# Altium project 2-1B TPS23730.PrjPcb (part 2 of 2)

## Sheet TPS23730 Page 1 Input Power.SchDoc
size A2; Date: Not shown in title block; ApprovedBy: Not shown in title block; CheckedBy: Not shown in title block; Author: Not shown in title block; CompanyName: Not shown in title block; Engineer: Not shown in title block; Organization: Not shown in title block; Address1: Not shown in title block; Address2: Not shown in title block; Address3: Not shown in title block; Address4: Not shown in title block; DocumentNumber: 2; Revision: Use project parameter SCH_Rev; SheetNumber: 2; SheetTotal: 3; PageSetup: Record=PageOptions¦CenterHorizontal=True¦CenterVertical=True¦PrintScale=1.00¦XCorrection=1.00¦YCorrection=1.00¦PrintKind=0¦BorderSize=5000000¦LeftOffset=0¦BottomOffset=0¦Orientation=2¦PaperLength=1000¦PaperWidth=1000¦Scale=100¦PaperSource=15¦PrintQuality=600¦MediaType=1¦DitherType=10¦PaperKind=Letter¦PrintScaleMode=1
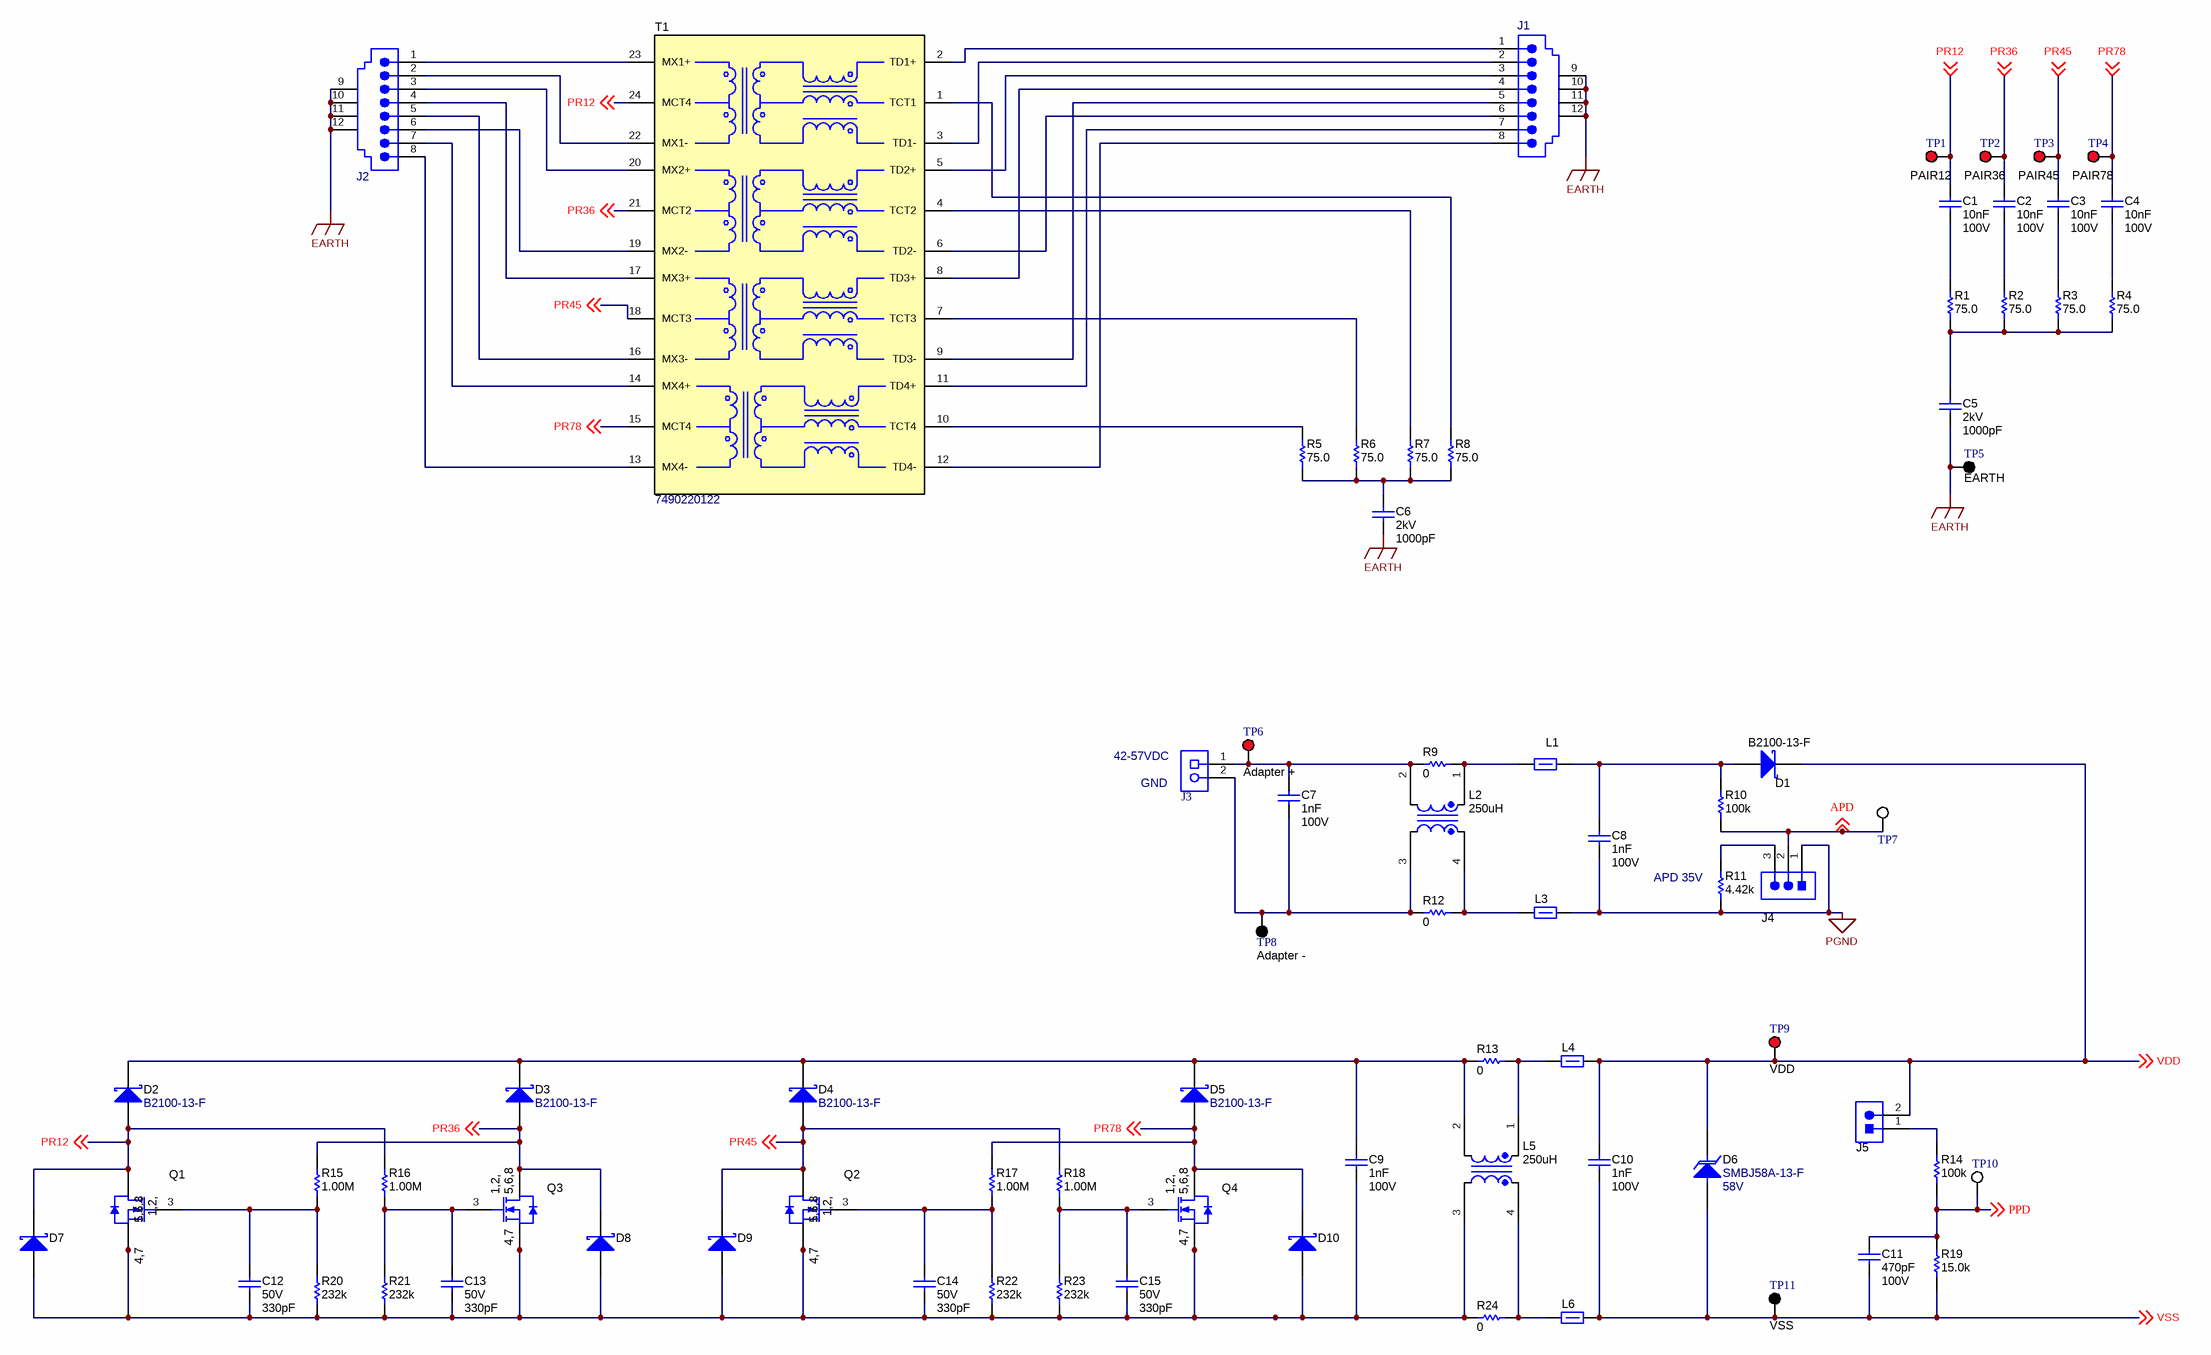
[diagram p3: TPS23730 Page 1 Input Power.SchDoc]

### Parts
C1  Cap_F: 10nF  VDC_V: 100V  [0603]  (hidden comment: CGA3E2X7R2A103K080AA)
C2  Cap_F: 10nF  VDC_V: 100V  [0603]  (hidden comment: CGA3E2X7R2A103K080AA)
C3  Cap_F: 10nF  VDC_V: 100V  [0603]  (hidden comment: CGA3E2X7R2A103K080AA)
C4  Cap_F: 10nF  VDC_V: 100V  [0603]  (hidden comment: CGA3E2X7R2A103K080AA)
C5  VDC_V: 2kV  ValueDisplayed: 1000pF  [1808]  (hidden comment: GR442QR73D102KW01L)
C6  VDC_V: 2kV  ValueDisplayed: 1000pF  [1808]  (hidden comment: GR442QR73D102KW01L)
C7  Cap_F: 1nF  VDC_V: 100V  [0603]  (hidden comment: C1608X7R2A102K080AA)
C8  Cap_F: 1nF  VDC_V: 100V  [0603]  (hidden comment: C1608X7R2A102K080AA)
C9  Cap_F: 1nF  VDC_V: 100V  [0603]  (hidden comment: C1608X7R2A102K080AA)
C10  Cap_F: 1nF  VDC_V: 100V  [0603]  (hidden comment: C1608X7R2A102K080AA)
C11  Cap_F: 470pF  VDC_V: 100V  [0805_HV]  (hidden comment: 08051C471KAT2A)
C12  VDC_V: 50V  ValueDisplayed: 330pF  [0603]  (hidden comment: 885012006060)
C13  VDC_V: 50V  ValueDisplayed: 330pF  [0603]  (hidden comment: 885012006060)
C14  VDC_V: 50V  ValueDisplayed: 330pF  [0603]  (hidden comment: 885012006060)
C15  VDC_V: 50V  ValueDisplayed: 330pF  [0603]  (hidden comment: 885012006060)
D1  PartNumber: B2100-13-F  [SMB]  (hidden comment: CMP-0028397-2)
D2  B2100-13-F  [SMB]
D3  B2100-13-F  [SMB]
D4  B2100-13-F  [SMB]
D5  B2100-13-F  [SMB]
D6  SMBJ58A-13-F  value 58V  [SMB]
D7  CMP-0028397-2  [SMB]  (value not drawn)
D8  CMP-0028397-2  [SMB]  (value not drawn)
D9  CMP-0028397-2  [SMB]  (value not drawn)
D10  CMP-0028397-2  [SMB]  (value not drawn)
J1  1-406541-1  [TEC_1-406541-1]  (value not drawn)
J2  1-406541-1  [TEC_1-406541-1]  (value not drawn)
J3  39357-0002  [MOLEX_39357-0002]  (value not drawn)
J4  5-146278-3  [TE_5-146278-3]  (value not drawn)
J5  PEC02SAAN  [CONN_PEC02SAAN]  (value not drawn)
L1  742792641  [0603]  (value not drawn)
L2  value 250uH  [WE-SL5]  (hidden comment: 744272251)
L3  742792641  [0603]  (value not drawn)
L4  742792641  [0603]  (value not drawn)
L5  value 250uH  [WE-SL5]  (hidden comment: 744272251)
L6  742792641  [0603]  (value not drawn)
Q1  CSD19538Q2  [DQK0006C]  (value not drawn)
Q2  CSD19538Q2  [DQK0006C]  (value not drawn)
Q3  CSD19538Q2  [DQK0006C]  (value not drawn)
Q4  CSD19538Q2  [DQK0006C]  (value not drawn)
R1  ValueDisplayed: 75.0  [0603]  (hidden comment: CRCW060375R0FKEA)
R2  ValueDisplayed: 75.0  [0603]  (hidden comment: CRCW060375R0FKEA)
R3  ValueDisplayed: 75.0  [0603]  (hidden comment: CRCW060375R0FKEA)
R4  ValueDisplayed: 75.0  [0603]  (hidden comment: CRCW060375R0FKEA)
R5  ValueDisplayed: 75.0  [0603]  (hidden comment: CRCW060375R0FKEA)
R6  ValueDisplayed: 75.0  [0603]  (hidden comment: CRCW060375R0FKEA)
R7  ValueDisplayed: 75.0  [0603]  (hidden comment: CRCW060375R0FKEA)
R8  ValueDisplayed: 75.0  [0603]  (hidden comment: CRCW060375R0FKEA)
R9  ValueDisplayed: 0  [0805_HV]  (hidden comment: PMR10EZPJ000)
R10  ValueDisplayed: 100k  [0603]  (hidden comment: CRCW0603100KFKEA)
R11  ValueDisplayed: 4.42k  [0603]  (hidden comment: CRCW06034K42FKEA)
R12  ValueDisplayed: 0  [0805_HV]  (hidden comment: PMR10EZPJ000)
R13  ValueDisplayed: 0  [0805_HV]  (hidden comment: PMR10EZPJ000)
R14  ValueDisplayed: 100k  [0603]  (hidden comment: CRCW0603100KFKEA)
R15  ValueDisplayed: 1.00M  [0603]  (hidden comment: CRCW06031M00FKEA)
R16  ValueDisplayed: 1.00M  [0603]  (hidden comment: CRCW06031M00FKEA)
R17  ValueDisplayed: 1.00M  [0603]  (hidden comment: CRCW06031M00FKEA)
R18  ValueDisplayed: 1.00M  [0603]  (hidden comment: CRCW06031M00FKEA)
R19  ValueDisplayed: 15.0k  [0603]  (hidden comment: CRCW060315K0FKEA)
R20  ValueDisplayed: 232k  [0603]  (hidden comment: CRCW0603232KFKEA)
R21  ValueDisplayed: 232k  [0603]  (hidden comment: CRCW0603232KFKEA)
R22  ValueDisplayed: 232k  [0603]  (hidden comment: CRCW0603232KFKEA)
R23  ValueDisplayed: 232k  [0603]  (hidden comment: CRCW0603232KFKEA)
R24  ValueDisplayed: 0  [0805_HV]  (hidden comment: PMR10EZPJ000)
T1  7490220122  [Wurth_7490220122]
TP1  PAIR12  [Keystone5010]
TP2  PAIR36  [Keystone5010]
TP3  PAIR45  [Keystone5010]
TP4  PAIR78  [Keystone5010]
TP5  EARTH  [Keystone5011]
TP6  Adapter +  [Keystone5000]
TP7  5002  [Keystone5002]  (value not drawn)
TP8  Adapter -  [Keystone5001]
TP9  VDD  [Keystone5000]
TP10  5002  [Keystone5002]  (value not drawn)
TP11  VSS  [Keystone5001]

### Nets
EARTH: C5.1 C6.1 J1.9 J1.10 J1.11 J1.12 J2.9 J2.10 J2.11 J2.12 TP5.1
PGND: C8.2 J4.1 L3.2 R11.1
APD: J4.2 R10.1 TP7.1 ; off-sheet APD
PPD: C11.1 R14.2 R19.2 TP10.1 ; off-sheet PPD
PR12: C1.2 D2.2(A) D7.1(K) Q1.1(D) Q1.2(D) Q1.5(D) Q1.6(D) Q1.8(D) R16.2 T1.24(MCT4) TP1.1 ; off-sheet PR12
PR36: C2.2 D3.2(A) D8.1(K) Q3.1(D) Q3.2(D) Q3.5(D) Q3.6(D) Q3.8(D) R15.2 T1.21(MCT2) TP2.1 ; off-sheet PR36
PR45: C3.2 D4.2(A) D9.1(K) Q2.1(D) Q2.2(D) Q2.5(D) Q2.6(D) Q2.8(D) R18.2 T1.18(MCT3) TP3.1 ; off-sheet PR45
PR78: C4.2 D5.2(A) D10.1(K) Q4.1(D) Q4.2(D) Q4.5(D) Q4.6(D) Q4.8(D) R17.2 T1.15(MCT4) TP4.1 ; off-sheet PR78
VDD: C10.1 D1.1(K) D6.1(K) J5.2 L4.2 TP9.1 ; off-sheet VDD
VSS: C10.2 C11.2 D6.2(A) L6.2 R19.1 TP11.1 ; off-sheet VSS
NetC1_1: C1.1 R1.1
NetC2_1: C2.1 R2.1
NetC3_1: C3.1 R3.1
NetC4_1: C4.1 R4.1
NetC5_2: C5.2 R1.2 R2.2 R3.2 R4.2
NetC6_2: C6.2 R5.2 R6.2 R7.2 R8.2
NetC7_1: C7.1 J3.1 L2.2 R9.1 TP6.1
NetC7_2: C7.2 J3.2 L2.3 R12.1 TP8.1
NetC8_1: C8.1 D1.2(A) L1.2 R10.2
NetC9_1: C9.1 D2.1(K) D3.1(K) D4.1(K) D5.1(K) L5.2 R13.1
NetC9_2: C9.2 C12.2 C13.2 C14.2 C15.2 D7.2(A) D8.2(A) D9.2(A) D10.2(A) L5.3 Q1.4(S) Q1.7(S) Q2.4(S) Q2.7(S) Q3.4(S) Q3.7(S) Q4.4(S) Q4.7(S) R20.1 R21.1 R22.1 R23.1 R24.1
NetC12_1: C12.1 Q1.3(G) R15.1 R20.2
NetC13_1: C13.1 Q3.3(G) R16.1 R21.2
NetC14_1: C14.1 Q2.3(G) R17.1 R22.2
NetC15_1: C15.1 Q4.3(G) R18.1 R23.2
NetJ1_1: J1.1 T1.2(TD1+)
NetJ1_2: J1.2 T1.3(TD1-)
NetJ1_3: J1.3 T1.5(TD2+)
NetJ1_4: J1.4 T1.8(TD3+)
NetJ1_5: J1.5 T1.9(TD3-)
NetJ1_6: J1.6 T1.6(TD2-)
NetJ1_7: J1.7 T1.11(TD4+)
NetJ1_8: J1.8 T1.12(TD4-)
NetJ2_1: J2.1 T1.23(MX1+)
NetJ2_2: J2.2 T1.22(MX1-)
NetJ2_3: J2.3 T1.20(MX2+)
NetJ2_4: J2.4 T1.17(MX3+)
NetJ2_5: J2.5 T1.16(MX3-)
NetJ2_6: J2.6 T1.19(MX2-)
NetJ2_7: J2.7 T1.14(MX4+)
NetJ2_8: J2.8 T1.13(MX4-)
NetJ4_3: J4.3 R11.2
NetJ5_1: J5.1 R14.1
NetL1_1: L1.1 L2.1 R9.2
NetL2_4: L2.4 L3.1 R12.2
NetL4_1: L4.1 L5.1 R13.2
NetL5_4: L5.4 L6.1 R24.2
NetR5_1: R5.1 T1.10(TCT4)
NetR6_1: R6.1 T1.7(TCT3)
NetR7_1: R7.1 T1.4(TCT2)
NetR8_1: R8.1 T1.1(TCT1)

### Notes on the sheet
- (near J3) 42-57VDC
- (near J3) GND
- (near R11) APD 35V

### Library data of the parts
C1-C4 = CMP-0007082-4: CAP, CERM, 0.01 uF, 100 V, +/- 10%, X7R, AEC-Q200 Grade 1, 0603; Manufacturer: TDK; TaMin_C: -55°C; ESR_ohm: 0.235428; Polarized: N; SizeAreaWB_mm2: 4.68; Value1: 0.235428 ohm; U/M: EA; Value: 0.01uF; TaMax_C: 125°C; SizeZ_mm: 1; SizeX_mm: 1.6; SizeY_mm: 0.8; SizeArea_mm2: 1.28; AEC Qualified: Y; IRMS_A: 396.995mA; AEC Category: Q200
C5 C6 = CMP-0009436-2: CAP, CERM, 1000 pF, 2000 V, +/- 10%, X7R, 1808; Manufacturer: MuRata; TaMin_C: -55°C; Polarized: N; SizeAreaWB_mm2: 16.5; Value1: Unknown; U/M: EA; Value: 1000pF; TaMax_C: 125°C; SizeZ_mm: 2.03; SizeX_mm: 4.5; SizeY_mm: 2; Value2: 2000V; SizeArea_mm2: 9; Cap_F: 1nF; AEC Category: Q200
C7-C10 = CMP-0007053-4: CAP, CERM, 1000 pF, 100 V, +/- 10%, X7R, 0603; Manufacturer: TDK; TaMin_C: -55°C; Polarized: N; SizeAreaWB_mm2: 4.68; Value1: Unknown; U/M: EA; Value: 1000pF; TaMax_C: 125°C; SizeZ_mm: 1; SizeX_mm: 1.6; SizeY_mm: 0.8; SizeArea_mm2: 1.28; AEC Category: Q200
C11 = CMP-0007557-2: CAP, CERM, 470 pF, 100 V, +/- 10%, X7R, 0805; Manufacturer: AVX; TaMin_C: -55°C; ESR_ohm: 0.454; Polarized: N; SizeAreaWB_mm2: 6.75; Value1: 0.454 ohm; U/M: EA; Value: 470pF; TaMax_C: 125°C; SizeZ_mm: 1.45; SizeX_mm: 2; SizeY_mm: 1.25; Cap_Case: 0805; SizeArea_mm2: 2.5; AEC Category: Q200
C12-C15 = CMP-0006823-4: CAP, CERM, 330 pF, 50 V, +/- 5%, C0G/NP0, 0603; Manufacturer: Wurth Elektronik; TaMin_C: -55°C; Polarized: N; SizeAreaWB_mm2: 4.68; Value1: Unknown; U/M: EA; Value: 330pF; TaMax_C: 125°C; SizeZ_mm: 1; SizeX_mm: 1.6; SizeY_mm: 0.8; SizeArea_mm2: 1.28; AEC Category: Q200
D1 = CMP-0028397-2: Diode, Schottky, 100 V, 2 A, SMB; Manufacturer: Diodes Inc.; Vf_V: 790mV; Value: 100V; Value1: 2A; Value2: 0.79V; TJmax_C: 150°C; RJC_CperW: 15; SizeArea_mm2: 21.336; Green_REACh: Passed; Green_Lifecycle: Active; SizeY_mm: 3.81; AEC Category: Q101; SizeZ_mm: 2.6; SizeAreaWB_mm2: 44.156; SizeX_mm: 5.6
D2-D5 = CMP-0028397-2: Diode, Schottky, 100 V, 2 A, SMB; Manufacturer: Diodes Inc.; Value2: 0.79V; Value1: 2A; SizeArea_mm2: 21.336; Value: 100V; Green_REACh: Passed; Green_Lifecycle: Active; Vf_V: 790mV; SizeY_mm: 3.81; AEC Category: Q101; SizeZ_mm: 2.6; TJmax_C: 150°C; RJC_CperW: 15; SizeAreaWB_mm2: 44.156; SizeX_mm: 5.6
D6 = CMP-0005583-3: Diode, TVS, Uni, 58 V, 93.6 Vc, SMB; Manufacturer: Diodes Inc.; Vbr_Max: 74.6V; AEC Category: Q101; Ppk: 600W; Vbr_Min: 64.4V; SizeX_mm: 5.6; SizeZ_mm: 2.6; SizeY_mm: 3.81; Ipp: 6.4A; Vc: 93.6V; SizeAreaWB_mm2: 44.156; SizeArea_mm2: 21.336
D7-D10 = CMP-0028397-2: Diode, Schottky, 100 V, 2 A, SMB; PartNumber: B2100-13-F; Manufacturer: Diodes Inc.; Vf_V: 790mV; Value: 100V; Value1: 2A; Value2: 0.79V; TJmax_C: 150°C; RJC_CperW: 15; SizeArea_mm2: 21.336; Green_REACh: Passed; Green_Lifecycle: Active; SizeY_mm: 3.81; AEC Category: Q101; SizeZ_mm: 2.6; SizeAreaWB_mm2: 44.156; SizeX_mm: 5.6
J1 J2 = CMP-0054918-1: RJ45, No LED, tab up, R/A, TH; Manufacturer: TE Connectivity; CNHeader: FALSE; Green_Lifecycle: Active; Green_REACh: Passed; ContactFinish: Gold; CT: TRUE
J3 = CMP-0055341-1: Terminal Block, 3.5 mm, 2x1, Tin, TH; Manufacturer: Molex; CNHeader: FALSE; Green_Lifecycle: Not Set; Green_REACh: Incomplete; CT: TRUE
J4 = CMP-0054951-1: Header, 100mil, 3x1, Tin, TH; Manufacturer: TE Connectivity; CNHeader: TRUE; Green_Lifecycle: Active; Green_REACh: Passed; CT: FALSE
J5 = CMP-0002337-1: Header, 100mil, 2x1, Tin, TH; Manufacturer: Sullins Connector Solutions; CNHeader: TRUE; Current_A: 3A; Green_Lifecycle: Not Set; Shrouded: N; Gender: Male; Green_REACh: Incomplete; Voltage_V: 1.8kV; Row_Count: 1; Pitch_mm: 2.54; CT: FALSE; Cert_UL: Y
L1 L3 L4 L6 = CMP-0003192-2: Ferrite Bead, 300 ohm @ 100 MHz, 2 A, 0603; Manufacturer: Wurth Elektronik; Ztyp@1GHz_Ohm: 273.989; ZTyp@100MHz_Ohm: 300; SizeAreaWB_mm2: 4.68; DCR_ohm: 0.15; Value1: 0.15 ohm; Value: 300 ohm; Imax_A: 2A; SizeZ_mm: 1; SizeX_mm: 1.6; SizeY_mm: 0.8; SizeArea_mm2: 1.28
L2 L5 = CMP-0013220-2: Coupled inductor, 250 uH,  A, 0.035 ohm, SMD; Manufacturer: Wurth Elektronik; DCR_ohm: 0.035; Ind_H: 250µH
Q1-Q4 = CMP-0000968-2: MOSFET, N-CH, 100 V, 4.5 A, DQK0006C (WSON-6); Alternate Manufacturer: None; Manufacturer: Texas Instruments; SizeZ_mm: 0.8; ChType: N; VdsMax_V: 100V; SizeX_mm: 2; SizeAreaWB_mm2: 9; Vgs_V: 20V; Value: 100V; SizeArea_mm2: 4; AEC Category: Q101; IdsMax_A: 4.5A; U/M: EA
R1 = CMP-0022590-4: RES, 75.0, 1%, 0.1 W, AEC-Q200 Grade 0, 0603; Manufacturer: Vishay-Dale; Power_W: 100mW; TempCo: 100 ppm/C; Value_Code: 75R0; Value: 75.0; EIA_Code: E96; Res_ohm: 75; SizeX_mm: 1.6; SizeY_mm: 0.8; SizeZ_mm: 1; Value2: 0.1W; SizeArea_mm2: 1.28; AEC Qualified: Y; VDC_V: 75V; AEC Category: Q200; AEC Grade: 0
R2-R8 = CMP-0022590-3: RES, 75.0, 1%, 0.1 W, 0603; Manufacturer: Vishay-Dale; Power_W: 100mW; TempCo: 100 ppm/C; Value_Code: 75R0; U/M: EA; Value: 75.0; EIA_Code: E96; Res_ohm: 75; SizeX_mm: 1.6; SizeY_mm: 0.8; SizeZ_mm: 1; Value2: 0.1W; SizeArea_mm2: 1.28; VDC_V: 75V; AEC Category: Q200
R9 R12 R13 R24 = CMP-0081857-1: RES, 0, 0%,  W, AEC-Q200 Grade 0, 0805; Manufacturer: Rohm; SizeAreaWB_mm2: 6.75; SizeArea_mm2: 2.5; AEC Qualified: Y; AEC Category: Q200; Value: 0; SizeZ_mm: 1.45; SizeY_mm: 1.25; SizeX_mm: 2
R10 R14 = CMP-0021990-4: RES, 100 k, 1%, 0.1 W, AEC-Q200 Grade 0, 0603; Manufacturer: Vishay-Dale; Power_W: 100mW; TempCo: 100 ppm/C; Value: 100k; EIA_Code: E96; SizeX_mm: 1.6; SizeY_mm: 0.8; SizeZ_mm: 1; Value2: 0.1W; SizeArea_mm2: 1.28; AEC Qualified: Y; VDC_V: 75V; AEC Category: Q200; AEC Grade: 0
R11 = CMP-0022453-4: RES, 4.42 k, 1%, 0.1 W, AEC-Q200 Grade 0, 0603; Manufacturer: Vishay-Dale; Power_W: 100mW; TempCo: 100 ppm/C; Value_Code: 4k42; Value: 4.42k; EIA_Code: E96; SizeX_mm: 1.6; SizeY_mm: 0.8; SizeZ_mm: 1; Value2: 0.1W; SizeArea_mm2: 1.28; AEC Qualified: Y; VDC_V: 75V; AEC Category: Q200; AEC Grade: 0
R15-R18 = CMP-0022138-4: RES, 1.00 M, 1%, 0.1 W, AEC-Q200 Grade 0, 0603; Manufacturer: Vishay-Dale; Power_W: 100mW; TempCo: 100 ppm/C; Value_Code: 1M00; Value: 1.00Meg; EIA_Code: E96; Res_ohm: 1M; SizeX_mm: 1.6; SizeY_mm: 0.8; SizeZ_mm: 1; Value2: 0.1W; SizeArea_mm2: 1.28; AEC Qualified: Y; VDC_V: 75V; AEC Category: Q200; AEC Grade: 0
R19 = CMP-0022066-4: RES, 15.0 k, 1%, 0.1 W, AEC-Q200 Grade 0, 0603; Manufacturer: Vishay-Dale; Power_W: 100mW; TempCo: 100 ppm/C; Value_Code: 15k0; Value: 15.0k; EIA_Code: E96; Res_ohm: 15k; SizeX_mm: 1.6; SizeY_mm: 0.8; SizeZ_mm: 1; Value2: 0.1W; SizeArea_mm2: 1.28; AEC Qualified: Y; VDC_V: 75V; AEC Category: Q200; AEC Grade: 0
R20-R23 = CMP-0022224-4: RES, 232 k, 1%, 0.1 W, AEC-Q200 Grade 0, 0603; Manufacturer: Vishay-Dale; Power_W: 100mW; TempCo: 100 ppm/C; Value: 232k; EIA_Code: E96; SizeX_mm: 1.6; SizeY_mm: 0.8; SizeZ_mm: 1; Value2: 0.1W; SizeArea_mm2: 1.28; AEC Qualified: Y; VDC_V: 75V; AEC Category: Q200; AEC Grade: 0
T1 = CMP-0030597-1: Transformer, 350 uH, SMT; Manufacturer: Wurth Elektronik; Value: 350uH; Ind_H: 350µH; Lp: 350
TP1-TP4 = CMP-0055147-1: Test Point, Multipurpose, Red, TH; Manufacturer: Keystone; CNHeader: FALSE; Green_Lifecycle: Active; Green_REACh: Passed; ContactFinish: Silver; CT: TRUE
TP5 = CMP-0055148-1: Test Point, Multipurpose, Black, TH; Manufacturer: Keystone; CNHeader: FALSE; Green_Lifecycle: Active; Green_REACh: Passed; ContactFinish: Silver; CT: TRUE
TP6 TP9 = CMP-0055137-1: Test Point, Miniature, Red, TH; Manufacturer: Keystone; CNHeader: FALSE; Green_Lifecycle: Active; Green_REACh: Passed; ContactFinish: Silver; CT: TRUE
TP7 TP10 = CMP-0055139-1: Test Point, Miniature, White, TH; Manufacturer: Keystone; CNHeader: FALSE; Green_Lifecycle: Active; Green_REACh: Passed; ContactFinish: Silver; CT: TRUE
TP8 TP11 = CMP-0055138-1: Test Point, Miniature, Black, TH; Manufacturer: Keystone; CNHeader: FALSE; Green_Lifecycle: Active; Green_REACh: Passed; ContactFinish: Silver; CT: TRUE

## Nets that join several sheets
PGND: Power Stage (41 pins), TPS23730 Page 1 Input Power (C8.2 J4.1 L3.2 R11.1)
APD: Power Stage (U1.5), TPS23730 Page 1 Input Power (J4.2 R10.1 TP7.1)
PPD: Power Stage (U1.19), TPS23730 Page 1 Input Power (C11.1 R14.2 R19.2 TP10.1)
VDD: Power Stage (8 pins), TPS23730 Page 1 Input Power (6 pins)
VSS: Power Stage (10 pins), TPS23730 Page 1 Input Power (6 pins)

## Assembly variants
5V -10A: not fitted C18 C26 C30 C37 C46 D7 D8 D9 D10 D11 D19 D21 D24 FID1 FID2 FID3 L2 L5 Q5 Q9 Q12 R29 R32 R35 R56 R57 R58; alternate parts C44 -> CMP-0007397-4, R43 -> CMP-0022126-4, R41 -> CMP-0022547-5, C47 -> CMP-0007877-2, C43 -> CMP-0006724-5, C45 -> CMP-0007438-4, R48 -> CMP-0021998-4, R45 -> CMP-0022743-5, R53 -> CMP-0022374-4, C28 -> CMP-0011104-1, C27 -> CMP-0083812-1, C29 -> CMP-0083812-1, C31 -> CMP-0007455-4, R31 -> CMP-0022446-5, L8 -> CMP-0064043-1, L7 -> CMP-0063965-1, C19 -> CMP-0008500-2, R28 -> CMP-0015987-3, C39 -> CMP-0007831-2, Q6 -> CMP-0000939-2, T2 -> CMP-0090287-1, Q8 -> CMP-0000706-1, U3 -> CMP-0032918-1, R46 -> CMP-0022865-5
12V -5A: not fitted C18 C26 C46 D7 D8 D9 D10 D11 D21 D24 L2 L5 Q9 Q12 R30 R56 R57 R58; alternate parts Q6 -> CMP-0000903-1, Q8 -> CMP-0000903-1, R43 -> CMP-0022895-5
4V: not fitted C18 C26 C30 C37 C46 D7 D8 D9 D10 D11 D19 D21 D24 FID1 FID2 FID3 L2 L5 Q5 Q9 Q12 R29 R32 R35 R56 R57 R58; alternate parts C44 -> CMP-0007397-4, R43 -> CMP-0022864-5, R41 -> CMP-0022547-5, C47 -> CMP-0007877-2, C43 -> CMP-0006724-5, C45 -> CMP-0007438-4, R48 -> CMP-0021998-4, R45 -> CMP-0021998-4, R53 -> CMP-0022454-4, U3 -> CMP-0032918-1, C28 -> CMP-0011104-1, C27 -> CMP-0083812-1, C29 -> CMP-0083812-1, C31 -> CMP-0007455-4, R31 -> CMP-0022446-5, L8 -> CMP-0064043-1, L7 -> CMP-0063965-1, C19 -> CMP-0008500-2, R28 -> CMP-0015987-3, C39 -> CMP-0007831-2, Q6 -> CMP-0000939-2, Q8 -> CMP-0000706-1, R46 -> CMP-0022865-5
